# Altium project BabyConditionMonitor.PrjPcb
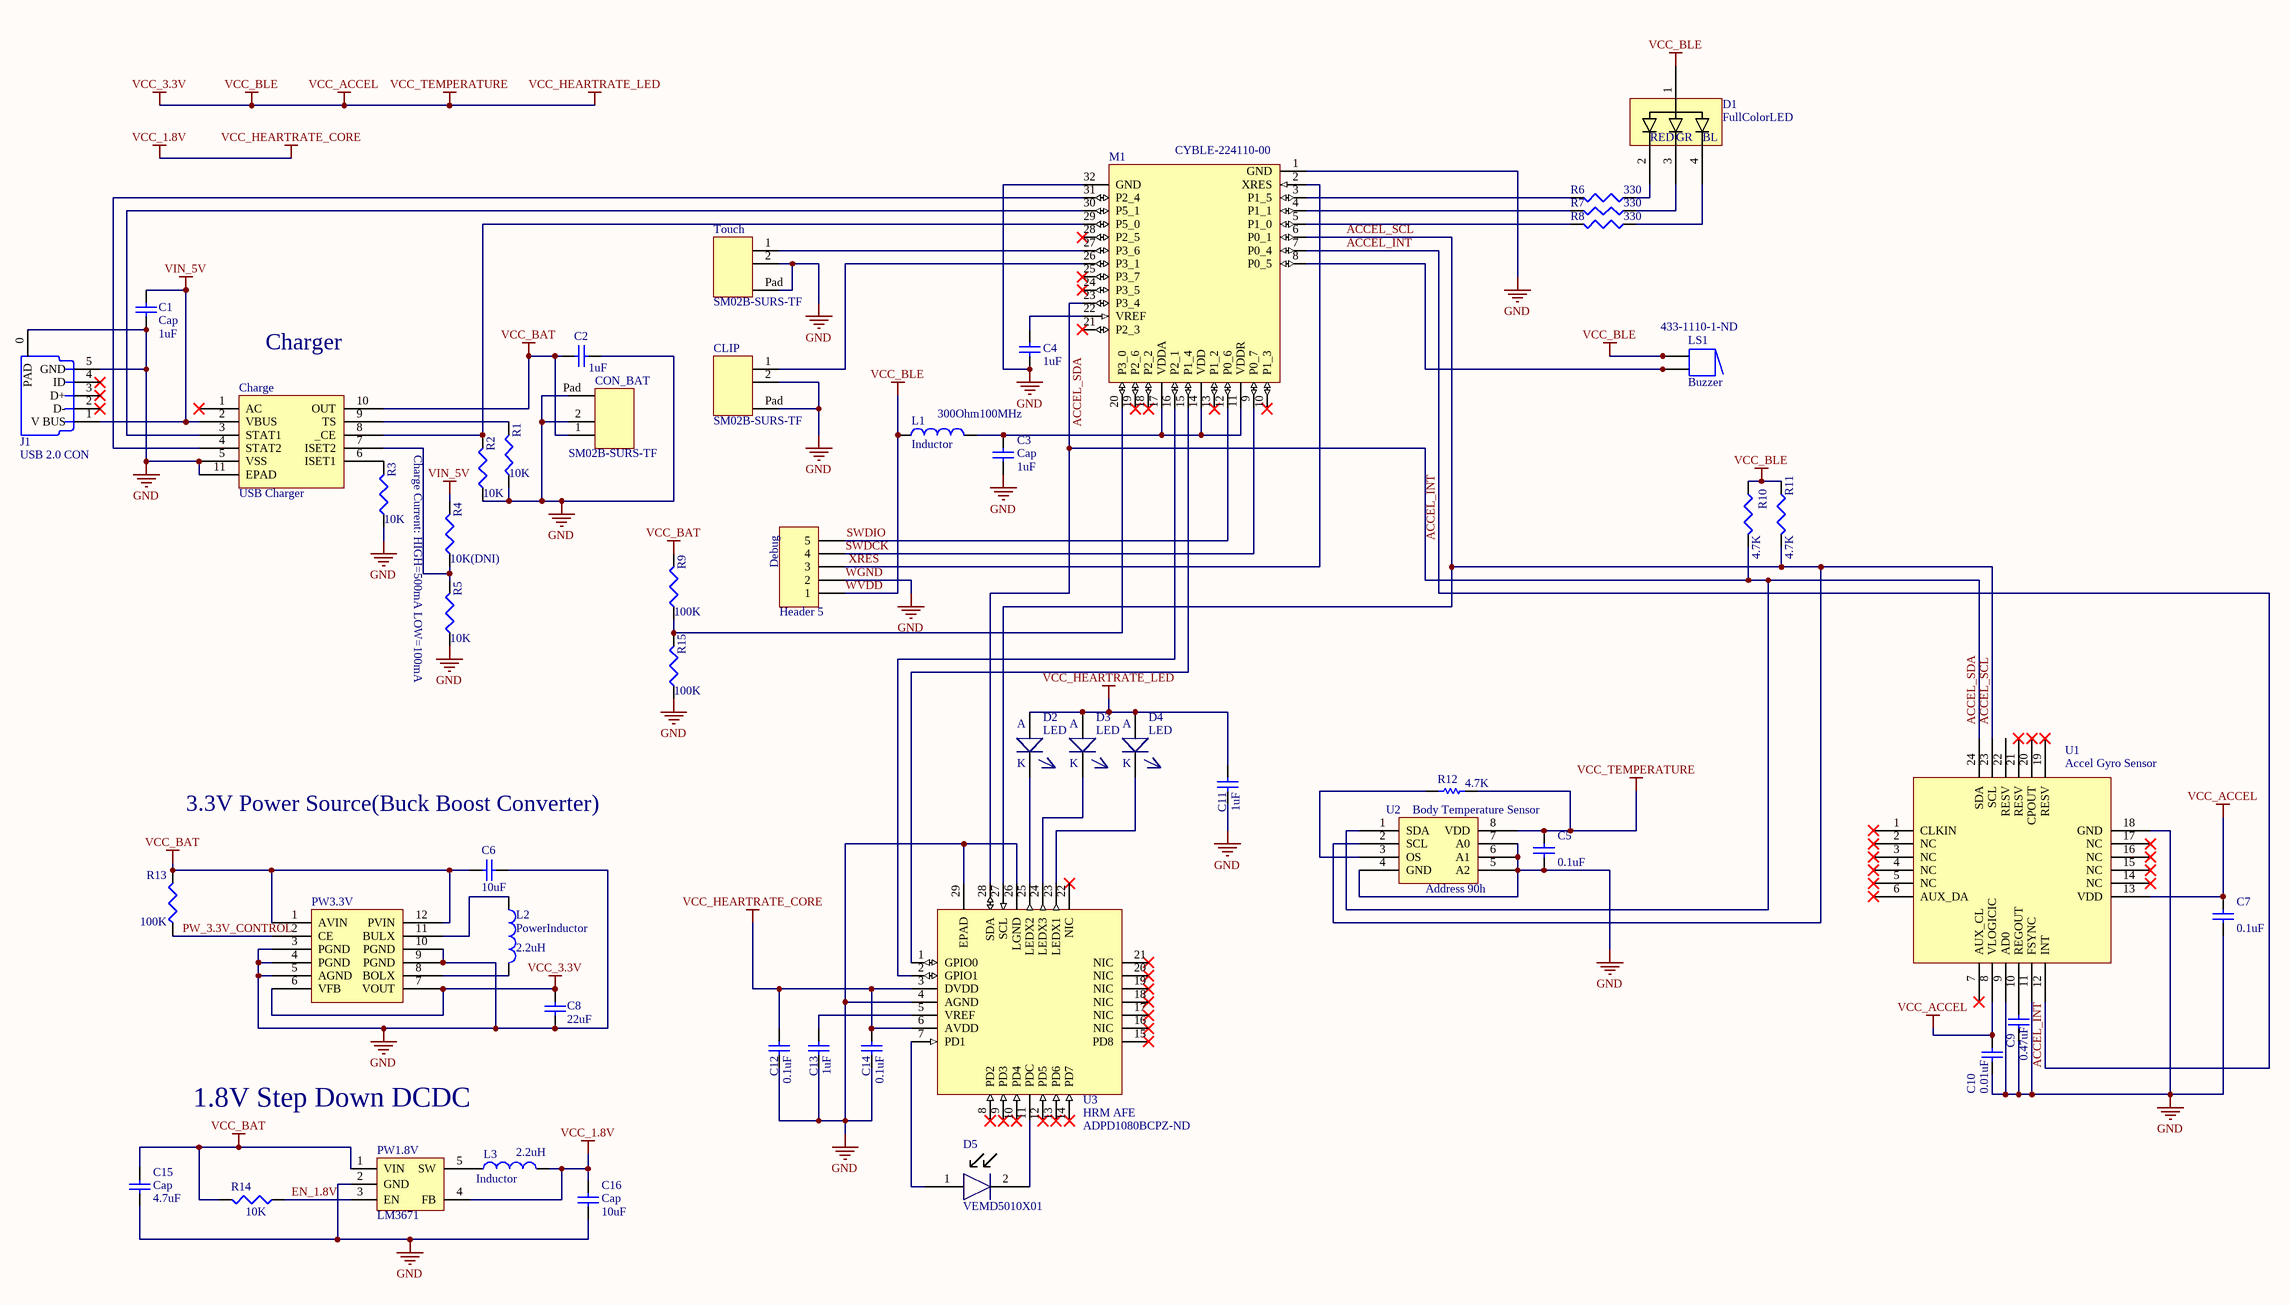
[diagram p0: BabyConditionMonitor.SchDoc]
1 sheet, 52 parts. Net scope: global (net labels, ports and power ports of the same name join across sheets).
Board files: BabyConditionMonitor.PcbDoc, BabyConditionMonitorEmbedd.PcbDoc

## Sheet BabyConditionMonitor.SchDoc
size A2

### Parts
C1  Cap  value 1uF  [1005[0402] High Density]
C2  value 1uF  [1005[0402] High Density]  (hidden comment: Cap)
C3  Cap  value 1uF  [1005[0402] High Density]
C4  value 1uF  [1005[0402] High Density]  (hidden comment: Cap)
C5  value 0.1uF  [1005[0402] High Density]  (hidden comment: Cap)
C6  value 10uF  [1005[0402] High Density]  (hidden comment: Cap)
C7  value 0.1uF  [1005[0402] High Density]  (hidden comment: Cap)
C8  value 22uF  [1608[0603]]  (hidden comment: Cap)
C9  value 0.47uF  [1005[0402] High Density]  (hidden comment: Cap)
C10  value 0.01uF  [1005[0402] High Density]  (hidden comment: Cap)
C11  value 1uF  [1005[0402] High Density]  (hidden comment: Cap)
C12  value 0.1uF  [1005[0402] High Density]  (hidden comment: Cap)
C13  value 1uF  [1005[0402] High Density]  (hidden comment: Cap)
C14  value 0.1uF  [1005[0402] High Density]  (hidden comment: Cap)
C15  Cap  value 4.7uF  [1005[0402] High Density]
C16  Cap  value 10uF  [1005[0402] High Density]
Charge  USB Charger  [BQ24020]
CLIP  SM02B-SURS-TF  [SM02B-SURS-TF]
CON_BAT  SM02B-SURS-TF  [SM02B-SURS-TF]
D1  FullColorLED  [fullColorLED SMT]
D2  LED  [1608[0603] -LED]
D3  LED  [1608[0603] -LED]
D4  LED  [1608[0603] -LED]
D5  VEMD5010X01  [OPT Sensor VEMD5010X01]
Debug  Header 5  [MHDR1X5]
J1  USB 2.0 CON  [MicroUSB WaterProof]
L1  Inductor  value 300Ohm100MHz  [INDC1608L]
L2  PowerInductor  value 2.2uH  [Powerinductor]
L3  Inductor  value 2.2uH  [INDC1608L]
LS1  Buzzer  Supplier Part Number 1: 433-1110-1-ND  [ST-0402T]
M1  CYBLE-224110-00  [CYBLE-224110-00]
PW1.8V  LM3671  [LM3671 SOT]
PW3.3V  Buck Boost Converter  [RP604x]  (value not drawn)
R1  value 10K  [1005[0402] High Density]  (hidden comment: Res3)
R2  value 10K  [1005[0402] High Density]  (hidden comment: Res3)
R3  value 10K  [1005[0402] High Density]  (hidden comment: Res3)
R4  value 10K(DNI)  [1005[0402] High Density]  (hidden comment: Res3)
R5  value 10K  [1005[0402] High Density]  (hidden comment: Res3)
R6  value 330  [1005[0402] High Density]  (hidden comment: Res3)
R7  value 330  [1005[0402] High Density]  (hidden comment: Res3)
R8  value 330  [1005[0402] High Density]  (hidden comment: Res3)
R9  value 100K  [1005[0402] High Density]  (hidden comment: Res3)
R10  value 4.7K  [1005[0402] High Density]  (hidden comment: Res3)
R11  value 4.7K  [1005[0402] High Density]  (hidden comment: Res3)
R12  value 4.7K  [1005[0402] High Density]  (hidden comment: Res Semi)
R13  value 100K  [1005[0402] High Density]  (hidden comment: Res3)
R14  value 10K  [1005[0402]]
R15  value 100K  [1005[0402] High Density]  (hidden comment: Res3)
Touch  SM02B-SURS-TF  [SM02B-SURS-TF]
U1  Accel Gyro Sensor  [MPU-6050]
U2  Body Temperature Sensor  [MAX30205]
U3  HRM AFE  Supplier Part Number 1: ADPD1080BCPZ-ND  [ADPD1080]

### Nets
VCC_1.8V: C12.2 C14.2 C16.2 L3.2 PW1.8V.4(FB) U3.3(DVDD) U3.6(AVDD)  [also labelled VCC_HEARTRATE_CORE]
VCC_BAT: C2.1 C6.2 C15.2 Charge.10(OUT) CON_BAT.1 PW1.8V.1(VIN) PW3.3V.1(AVIN) PW3.3V.12(PVIN) R9.2 R13.2 R14.2
VIN_5V: C1.1 Charge.2(VBUS) J1.1(V_BUS) R4.2
WGND: C1.2 C2.2 C3.1 C4.1 C5.1 C6.1 C7.1 C8.2 C9.1 C10.1 C11.1 C12.1 C13.1 C14.1 C15.1 C16.1 Charge.5(VSS) Charge.11(EPAD) CLIP.2 CLIP.Pad CON_BAT.2 CON_BAT.Pad Debug.2 J1.0(PAD) J1.5(GND) M1.1(GND) M1.32(GND) PW1.8V.2(GND) PW3.3V.3(PGND) PW3.3V.4(PGND) PW3.3V.5(AGND) PW3.3V.9(PGND) PW3.3V.10(PGND) R1.1 R2.1 R3.1 R5.1 R15.1 Touch.2 Touch.Pad U1.9(AD0) U1.11(FSYNC) U1.18(GND) U2.4(GND) U2.5(A2) U2.6(A1) U2.7(A0) U3.4(AGND) U3.26(LGND) U3.29(EPAD)  [also labelled GND]
WVDD: C5.2 C7.2 C8.1 C10.2 C11.2 D1.1 D2.1 D3.1 D4.1 Debug.1 L1.1 LS1.1 LS1.1A PW3.3V.6(VFB) PW3.3V.7(VOUT) R10.1 R11.1 R12.1 U1.8(VLOGICIC) U1.13(VDD) U2.8(VDD)  [also labelled VCC_3.3V, VCC_ACCEL, VCC_BLE, VCC_HEARTRATE_LED, VCC_TEMPERATURE]
ACCEL_INT: M1.7(P0_4) U1.12(INT)
ACCEL_SCL: M1.6(P0_1) R11.2 U1.23(SCL) U2.2(SCL) U3.27(SCL)
ACCEL_SDA: M1.23(P3_4) R10.2 U1.24(SDA) U2.1(SDA) U3.28(SDA)
EN_1.8V: PW1.8V.3(EN) R14.1
PW_3.3V_CONTROL: PW3.3V.2(CE) R13.1
SWDCK: Debug.4 M1.9(P0_7)
SWDIO: Debug.5 M1.12(P0_6)
XRES: Debug.3 M1.2(XRES)
NetC3_2: C3.2 L1.2 M1.11(VDDR) M1.14(VDD) M1.17(VDDA)
NetC4_2: C4.2 M1.22(VREF)
NetC9_2: C9.2 U1.10(REGOUT)
NetC13_2: C13.2 U3.5(VREF)
NetCharge_3: Charge.3(STAT1) M1.30(P5_1)
NetCharge_4: Charge.4(STAT2) M1.31(P2_4)
NetCharge_6: Charge.6(ISET1) R3.2
NetCharge_7: Charge.7(ISET2) R4.1 R5.2
NetCharge_8: Charge.8(_CE) M1.29(P5_0) R2.2
NetCharge_9: Charge.9(TS) R1.2
NetCLIP_1: CLIP.1 M1.26(P3_1)
NetD1_2: D1.2 R6.1
NetD1_3: D1.3 R7.1
NetD1_4: D1.4 R8.1
NetD2_2: D2.2 U3.25(LEDX2)
NetD3_2: D3.2 U3.24(LEDX3)
NetD4_2: D4.2 U3.23(LEDX1)
NetD5_1: D5.1 U3.7(PD1)
NetD5_2: D5.2 U3.11(PDC)
NetL2_1: L2.1 PW3.3V.11(BULX)
NetL2_2: L2.2 PW3.3V.8(BOLX)
NetL3_1: L3.1 PW1.8V.5(SW)
NetLS1_2: LS1.2 LS1.2A M1.8(P0_5)
NetM1_3: M1.3(P1_5) R6.2
NetM1_4: M1.4(P1_1) R7.2
NetM1_5: M1.5(P1_0) R8.2
NetM1_15: M1.15(P1_4) U3.1(GPIO0)
NetM1_16: M1.16(P2_1) U3.2(GPIO1)
NetM1_20: M1.20(P3_0) R9.1 R15.2
NetM1_27: M1.27(P3_6) Touch.1
NetR12_2: R12.2 U2.3(OS)

Not connected (* = marked no-connect by the designer): Charge 1(AC)*; J1 2(D-)* 3(D+)* 4(ID)*; M1 10(P1_3)* 13(P1_2)* 18(P2_2)* 19(P2_6)* 21(P2_3)* 24(P3_5)* 25(P3_7)* 28(P2_5)*; U1 1(CLKIN)* 2(NC)* 3(NC)* 4(NC)* 5(NC)* 6(AUX_DA)* 7(AUX_CL)* 14(NC)* 15(NC)* 16(NC)* 17(NC)* 19(RESV)* 20(CPOUT)* 21(RESV)* 22(RESV); U3 8(PD2)* 9(PD3)* 10(PD4)* 12(PD5)* 13(PD6)* 14(PD7)* 15(PD8)* 16(NIC)* 17(NIC)* 18(NIC)* 19(NIC)* 20(NIC)* 21(NIC)* 22(NIC)*

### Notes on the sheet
- Charger
- Charge Current: HIGH=500mA LOW=100mA
- 3.3V Power Source(Buck Boost Converter)
- (near U2) Address 90h
- 1.8V Step Down DCDC

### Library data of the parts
C1-C16 = Cap: Capacitor
Charge = BQ2402X
D1 = FullColorLED: PartNo: OSTB0603C1C-A
D2-D4 = LED: LED SMD
Debug = Header 5: Header, 5-Pin
J1 = USBConnector: USB2.0 Connector; PartNo: DX4RNW5HJ3R1000; Manufacture: Molex; PCB_Layout: Complies with Manufacturer's Recommendation.
L1 = Inductor: Code_IEC: 1005
L2 = PowerInductor: PartNo: CDRH2D14NP-2R2NC; Manufacture: Sumida
L3 = Inductor: PartNo: ASMPH-0603-2R2M-T; Manufacture: Abracon-LLC; Code_IEC: 1005
LS1 = Buzzer: Magnetic Transducer Buzzer
M1 = CYBLE-224110-00: BLE Module Long Range
PW1.8V = LM3671: StepDownDCDC; Manufacture: Texas Instruments
PW3.3V = RP604x: Manufacture: Ricoh; PartNo: RP604K331A
R1-R11 R13-R15 = Res3: Resistor
R12 = Res Semi: Semiconductor Resistor
U1 = MPU-6050: Manufacture: TDK InvenSense; PartNo: ICM-20689
U2 = MAX30205: Body Temperature Sebsor; Manufature: Maxim
U3 = ADPD1080: Manufacturer: Analog Devices; Manufacturer Part Number: ADPD1080BCPZ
